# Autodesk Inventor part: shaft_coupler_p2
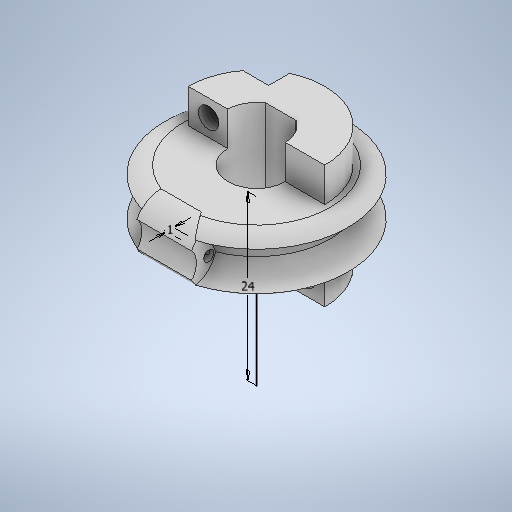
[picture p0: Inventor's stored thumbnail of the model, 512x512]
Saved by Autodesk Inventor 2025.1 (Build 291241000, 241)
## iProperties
Created: 2025-03
Part Number: shaft_coupler_p2
Material: Genérico
Document SubType Name: Modeling
Designer: Usuario
Density: 1 g/cm^3
Appearance: Valor por defecto
Author: Usuario
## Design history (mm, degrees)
sketch "Boceto1"
  geometry: L1 (-0.079, -4.178)-(-0.079, -3.578); L2 (-0.079, -3.578)-(2.2, -3.578); L3 (-0.079, -3.578)-(-2.2, -3.578); C1 r 10 at (0, 0); A1 r 4.2 centre (0, 0) between (2.2, -3.578) and (-2.2, -3.578); 1 further point
  constraints: 6 end point, 2 centre point, 2 coincident, 2 point on circle, 1 perpendicular, 1 point on line, 1 vertical
  dimensions: "d0" = 8.4 diameter of A1; "d1" = 20 diameter of C1; "d2" = 0.6 distance of L1.start L1.end
extrude "Extrusión1" new body sketch "Boceto1" stored distance "d3" = 8; taper "d4" = 0 deg
sketch "Boceto2"
  geometry: L1 (-2.2, 3.578)-(2.2, 3.578) reference; L2 (2.2, 3.578)-(-2.2, 3.578); L3 (-4.2, 0)-(-10, 0); L4 (4.05, 0)-(10, 0); A1 r 10 centre (0, 0) between (10, 0) and (-10, 0); A2 r 4.2 centre (0, 0) between (4.2, 0) and (2.2, 3.578); A3 r 4.2 centre (0, 0) between (-2.2, 3.578) and (-4.2, 0); 2 further points
  constraints: 6 end point, 6 point on circle, 3 centre point, 2 coincident, 1 collinear, 1 horizontal, 1 point on line
extrude "Extrusión2" join sketch "Boceto2" distance "d5" = 5; taper "d6" = 0 deg
node "Plano de trabajo1"
mirror "Simetría1"
node "Plano de trabajo2"
sketch "Boceto3"
  geometry: L1 (0, 0)-(5, 0) reference; L2 (0, 0)-(0, 2.9); L3 (0, 5.8)-(0, 0) reference; L4 (0, 2.9)-(2.5, 2.9); C1 r 1.5 at (2.5, 2.9); 1 further point
  constraints: 4 end point, 1 centre point, 1 coincident, 1 midpoint, 1 perpendicular
  dimensions: "d7" = 2.9 distance of L1.start L2.end (derived); "d8" = 2.5 distance of L2.end L4.end; "d9" = 3 diameter of C1
extrude "screw1" cut sketch "Boceto3" distance "d10" = 9; taper "d11" = 0 deg
node "Plano de trabajo3"
sketch "Boceto4"
  geometry: C1 r 1.5 at (2.5, 2.9) reference; C2 r 1.5 at (2.5, 2.9); C3 r 3.75 at (2.5, 2.9); 1 further point
  constraints: 2 centre point, 2 coincident, 1 concentric
  dimensions: "d15" = 7.5 diameter of C3
extrude "Extrusión4" cut sketch "Boceto4" distance "d13" = 9; taper "d14" = 0 deg
sketch "Boceto5"
  geometry: L1 (-8, 20)-(-13, 20) reference; L2 (-13, 20)-(-13, 17.025); L3 (-13, 17.025)-(-10.5, 17.025); C1 r 1.5 at (-10.5, 17.025); 1 further point
  constraints: 4 end point, 1 centre point, 1 coincident, 1 perpendicular, 1 vertical
  dimensions: "d16" = 2.975 distance of L1.end L2.end; "d17" = 2.5 distance of L2.end L3.end; "d18" = 3 diameter of C1
extrude "screw2" cut sketch "Boceto5" distance "d19" = 9; taper "d20" = 0 deg
sketch "Boceto6"
  geometry: C1 r 1.5 at (-10.5, 17.025) reference; C2 r 3.75 at (-10.5, 17.025); C3 r 2 at (-10.5, 17.025); 1 further point
  constraints: 2 centre point, 2 coincident
  dimensions: "d21" = 7.5 diameter of C2
extrude "Extrusión6" cut sketch "Boceto6" distance "d22" = 9; taper "d23" = 0 deg
node "Plano de trabajo5"
sketch "Boceto7"
  geometry: L1 (0, -10)-(0, -11); A1 r 10 centre (0, 0) between (-10, 0) and (10, 0) reference; 1 further point
  constraints: 2 end point, 1 point on circle, 1 vertical
  dimensions: "d29" = 1 distance of L1.start L1.end
node "Plano de trabajo6"
sketch "Boceto8"
  geometry: L1 (0, 0)-(1, 0); L2 (0, 4)-(0, -4); L3 (0, -4)-(0, 4) reference; C1 r 0.75 at (1, 0); A1 r 4 centre (0, 0) between (0, -4) and (0, 4); 1 further point
  constraints: 6 end point, 2 centre point, 2 coincident, 2 point on circle, 1 horizontal
  dimensions: "d31" = 1 distance of L1.start L1.end; "d32" = 1.5 diameter of C1
extrude "Extrusión7" join sketch "Boceto8" stored distance "d33" = 8; taper "d34" = 0 deg
feature "Engrosado1" dims "d35" = 1, "d36" = 1
feature "Engrosado2" dims "d37" = 1, "d38" = 1
node "Plano de trabajo7"
feature "Rosca4" dims "d45" = 6, "d46" = 0
feature "Rosca5" dims "d47" = 6, "d48" = 0
node "Plano de trabajo8"
sketch "Boceto11"
  geometry: L1 (-0.835, -4)-(-0.835, 4) reference; L2 (-0.835, 4)-(-0.835, -4); L3 (0, -4)-(-0.835, -4) reference; L4 (-0.835, -4)-(0, -4); L5 (0, 4)-(-0.835, 4) reference; L6 (-0.835, 4)-(0, 4); L7 (0, 0)-(2.828, -2.828); L8 (0, 0)-(4, 0); A1 r 4 centre (0, 0) between (0, -4) and (0, 4) reference; A2 r 4.2 centre (4.026, 1.197) between (0, 0) and (2.828, -2.828); A3 r 4.2 centre (4.026, -1.197) between (2.828, 2.828) and (0, 0); 2 further points
  constraints: 10 end point, 5 point on circle, 2 centre point, 2 collinear, 2 symmetric about line, 1 equal length, 1 horizontal, 1 vertical, 1 other
  dimensions: "d51" = 45 deg angle of L7 L8; "d52" = 4.2 radius of A2
sketch "Boceto12"
  geometry: L1 (-4, 10)-(20, 10)
  constraints: 2 end point, 1 horizontal
  dimensions: "d53" = 24 distance of L1.start L1.end
revolve "Revolución1" stored, may be unused: angle "d54" = 326 deg
sketch "Boceto13"
  geometry: A1 r 4 centre (0, 0) between (2.828, -2.828) and (2.828, 2.828) reference; A2 r 4.2 centre (4.026, 1.197) between (0, 0) and (2.828, -2.828) reference; A3 r 4 centre (0, 0) between (3.835, -1.138) and (3.835, 1.138); A4 r 4 centre (0, 0) between (2.828, -2.828) and (2.828, 2.828) reference; A5 r 4 centre (0, 0) between (2.828, -2.828) and (3.536, 1.87); 5 further points
  constraints: 9 point on circle, 2 centre point, 2 coincident, 2 concentric, 4 other
extrude "Extrusión9" cut sketch "Boceto13" distance "d56" = 8; taper "d57" = 0 deg
node "Sólido1"
other parameters: "d12" = 6, "d30" = 90 deg, "d39" = 14, "d49" = 0
